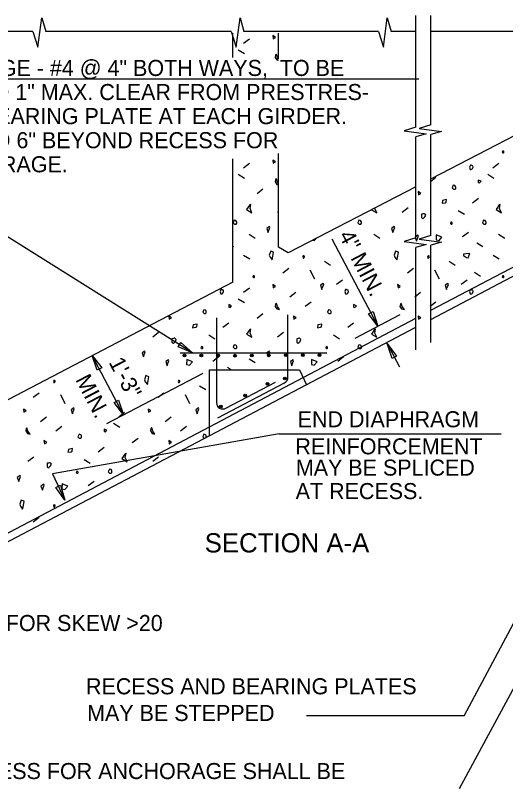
# Model space of a CAD drawing. Extents: x 0 to 22.7, y 0 to 15.7.
# Drawn here: x 3.45 to 6.629, y 5.449 to 10.447 of the extents above; entities that cross this region are included whole.
import ezdxf

# ---------------------------------------------------------------- set-up
doc = ezdxf.new("R2010")
doc.units = 0
for name, color, linetype in [('BRDG_ANNO_General-Notes', 7, 'Continuous'), ('BRDG_BASE_Obj-Line', 7, 'Continuous'), ('BRDG_BASE_Pattern', 7, 'Continuous'), ('BRDG_BASE_Rebar', 7, 'Continuous')]:
    doc.layers.add(name, color=color, linetype=linetype)

msp = doc.modelspace()

# ---------------------------------------------------------------- linework, layer by layer
at = {"layer": 'BRDG_ANNO_General-Notes'}
for p, q in [((6.0675, 10.0336), (2.7891, 10.0336)), ((4.5997, 8.2579), (2.7891, 9.3907)), ((5.503, 8.9974), (5.8017, 8.4298)), ((5.9439, 8.5038), (5.6511, 8.3507)), ((5.7404, 8.5105), (5.7698, 8.526)), ((5.8017, 8.4298), (5.7404, 8.5105)), ((5.7698, 8.526), (5.8017, 8.4298)), ((4.5061, 8.2968), (4.5237, 8.3251)), ((4.5997, 8.2579), (4.5061, 8.2968)), ((4.5237, 8.3251), (4.5997, 8.2579)), ((5.8609, 8.3171), (5.9403, 8.1663)), ((5.8928, 8.2208), (5.8609, 8.3171)), ((5.8609, 8.3171), (5.9222, 8.2364)), ((4.1515, 7.854), (3.9493, 8.2408)), ((3.9809, 8.1444), (3.9493, 8.2408)), ((3.9493, 8.2408), (4.0104, 8.1599)), ((5.9222, 8.2364), (5.8928, 8.2208)), ((4.0104, 8.1599), (3.9809, 8.1444)), ((4.6656, 8.1228), (4.0408, 7.7961)), ((4.0904, 7.9349), (4.1199, 7.9504)), ((4.1199, 7.9504), (4.1515, 7.854)), ((4.1515, 7.854), (4.0904, 7.9349)), ((5.1611, 7.7313), (3.6905, 7.473)), ((5.1611, 7.7313), (6.5995, 7.7313)), ((6.3616, 5.9025), (7.2128, 7.5057)), ((3.6905, 7.473), (3.7699, 7.3006)), ((3.7129, 7.3844), (3.7432, 7.3984)), ((3.7432, 7.3984), (3.7699, 7.3006)), ((3.7699, 7.3006), (3.7129, 7.3844)), ((6.3306, 5.43), (7.1358, 6.9271)), ((6.3616, 5.9025), (5.3378, 5.9025))]:
    msp.add_line(p, q, dxfattribs=at)
at = {"layer": 'BRDG_BASE_Obj-Line'}
for p, q in [((6.0466, 10.1917), (6.0466, 10.4467)), ((6.1455, 10.1917), (6.1455, 10.4467)), ((3.5964, 10.2407), (3.6219, 10.4317)), ((3.6219, 10.4317), (3.6476, 10.3412)), ((4.8815, 10.2406), (4.907, 10.4317)), ((4.907, 10.4317), (4.9327, 10.3412)), ((5.8365, 10.2407), (5.862, 10.4317)), ((5.862, 10.4317), (5.8877, 10.3412)), ((3.5639, 10.3412), (2.6926, 10.3412)), ((3.5639, 10.3412), (3.5964, 10.2407)), ((4.2125, 10.3412), (3.6476, 10.3412)), ((4.849, 10.3412), (4.2125, 10.3412)), ((4.849, 10.3412), (4.8815, 10.2406)), ((4.8611, 10.1728), (4.8611, 10.332)), ((5.804, 10.3412), (4.9327, 10.3412)), ((5.157, 10.1661), (5.157, 10.332)), ((5.804, 10.3412), (5.8365, 10.2407)), ((6.0467, 10.3412), (5.8877, 10.3412)), ((6.0466, 9.7217), (6.0466, 10.332)), ((6.6021, 10.3412), (6.1455, 10.3412)), ((6.1455, 9.7369), (6.1455, 10.332)), ((7.2386, 10.3412), (6.6021, 10.3412)), ((7.0631, 9.8613), (6.1473, 9.3866)), ((6.0466, 9.7217), (5.9708, 9.6971)), ((5.9708, 9.6971), (6.1144, 9.678)), ((6.1455, 9.7369), (6.0697, 9.7123)), ((6.0697, 9.7123), (6.2134, 9.6932)), ((6.1144, 9.678), (6.0466, 9.6587)), ((6.0466, 9.0042), (6.0466, 9.6587)), ((6.2134, 9.6932), (6.1455, 9.6739)), ((6.1455, 9.0194), (6.1455, 9.6739)), ((5.157, 8.9422), (5.157, 9.5498)), ((4.8611, 8.7151), (4.8611, 9.5166)), ((6.047, 9.3346), (5.219, 8.9054)), ((6.144, 8.4744), (7.5139, 9.1952)), ((6.0466, 9.0042), (5.9708, 8.9795)), ((6.1455, 9.0194), (6.0697, 8.9947)), ((5.9708, 8.9795), (6.1144, 8.9605)), ((6.1144, 8.9605), (6.0466, 8.9411)), ((6.0697, 8.9947), (6.2134, 8.9757)), ((6.2134, 8.9757), (6.1455, 8.9563)), ((6.1455, 8.3238), (6.1455, 8.9563)), ((5.219, 8.9054), (5.157, 8.9422)), ((6.0466, 8.2762), (6.0466, 8.9411)), ((4.8611, 8.7151), (3.3593, 7.9299)), ((2.6161, 6.6182), (6.0466, 8.4231)), ((4.7089, 7.7195), (4.7089, 8.1476)), ((4.7089, 8.1476), (5.2934, 8.1476)), ((5.2934, 8.1476), (5.3384, 8.0497))]:
    msp.add_line(p, q, dxfattribs=at)
at = {"layer": 'BRDG_BASE_Pattern'}
for p, q in [((4.9677, 10.2934), (4.9292, 10.2641)), ((4.8957, 10.2241), (4.9353, 10.1991)), ((4.9677, 9.4854), (4.9292, 9.4561)), ((6.5853, 9.4854), (6.5468, 9.4561)), ((4.8957, 9.4161), (4.9353, 9.3911)), ((6.5133, 9.4161), (6.5529, 9.3911)), ((6.1776, 9.3946), (6.1391, 9.3653)), ((5.0559, 9.3182), (5.0174, 9.2889)), ((6.4526, 9.2584), (6.4141, 9.2291)), ((5.9968, 9.1972), (5.9583, 9.1679)), ((5.157, 9.1736), (5.1495, 9.1679)), ((6.3222, 9.1815), (6.3618, 9.1566)), ((4.9662, 9.0267), (5.0057, 9.0018)), ((5.775, 9.0267), (5.8145, 9.0018)), ((6.3878, 9.0386), (6.3493, 9.0093)), ((6.5838, 9.0267), (6.6233, 9.0018)), ((4.8611, 8.9494), (4.8649, 8.947)), ((6.4429, 8.972), (6.4825, 8.947)), ((4.9303, 8.8915), (4.9698, 8.8664)), ((5.454, 8.8522), (5.4935, 8.8272)), ((6.2628, 8.8522), (6.3023, 8.8272)), ((6.5478, 8.8915), (6.5874, 8.8664)), ((5.2227, 8.8045), (5.1842, 8.7752)), ((5.36, 8.7956), (5.3893, 8.7368)), ((6.0315, 8.8045), (5.993, 8.7752)), ((6.1688, 8.7956), (6.1981, 8.7368)), ((6.4279, 8.7799), (6.4674, 8.7549)), ((5.5707, 8.7294), (5.5322, 8.7002)), ((6.3795, 8.7294), (6.341, 8.7002)), ((4.9677, 8.6774), (4.9292, 8.6482)), ((5.2694, 8.6479), (5.2309, 8.6186)), ((6.0782, 8.6479), (6.0397, 8.6186)), ((4.8957, 8.6082), (4.9353, 8.5832)), ((5.3689, 8.5867), (5.3303, 8.5574)), ((6.1776, 8.5867), (6.1391, 8.5574)), ((5.0559, 8.5102), (5.0174, 8.4809)), ((4.835, 8.4505), (4.7965, 8.4211)), ((5.6438, 8.4505), (5.6053, 8.4211)), ((4.3792, 8.3893), (4.3407, 8.36)), ((4.7046, 8.3735), (4.7442, 8.3486)), ((5.188, 8.3893), (5.1495, 8.36)), ((5.5134, 8.3735), (5.553, 8.3486)), ((4.7702, 8.2306), (4.7317, 8.2014)), ((4.9662, 8.2187), (5.0057, 8.1939)), ((5.579, 8.2306), (5.5405, 8.2014)), ((4.8253, 8.1641), (4.8515, 8.1476)), ((3.6052, 7.9965), (3.5667, 7.9672)), ((4.414, 7.9965), (4.3754, 7.9672)), ((4.6452, 8.0442), (4.6848, 8.0192)), ((3.7424, 7.9876), (3.7718, 7.9288)), ((4.5512, 7.9876), (4.5805, 7.9288)), ((4.1589, 7.8695), (4.1204, 7.8402)), ((3.6518, 7.8399), (3.6133, 7.8107)), ((4.087, 7.8003), (4.1266, 7.7753)), ((4.4606, 7.8399), (4.4221, 7.8107)), ((3.7512, 7.7787), (3.7128, 7.7494)), ((4.5601, 7.7787), (4.5216, 7.7494)), ((4.2472, 7.7022), (4.2086, 7.673)), ((4.0263, 7.6425), (3.9877, 7.6132)), ((3.5704, 7.5813), (3.5319, 7.552)), ((3.8958, 7.5656), (3.9354, 7.5406)), ((4.3792, 7.5813), (4.3407, 7.552)), ((3.9614, 7.4227), (3.9229, 7.3934)), ((3.6052, 7.1885), (3.5667, 7.1593))]:
    msp.add_line(p, q, dxfattribs=at)
for points in [[(5.12, 10.316), (5.1229, 10.2953), (5.1377, 10.3042)], [(6.6104, 9.567), (6.6067, 9.5589), (6.611, 9.5544), (6.6164, 9.5544), (6.6185, 9.5568), (6.6185, 9.5611), (6.6178, 9.5632), (6.6155, 9.5656)], [(5.12, 9.508), (5.1229, 9.4873), (5.1377, 9.4962)], [(6.3949, 9.4623), (6.3996, 9.4476), (6.4038, 9.4476), (6.4098, 9.4491), (6.4142, 9.4533), (6.4184, 9.4623), (6.4172, 9.4711), (6.4098, 9.4726), (6.4067, 9.4757), (6.4008, 9.4757)], [(6.4523, 9.3783), (6.4516, 9.3624), (6.4611, 9.3602), (6.4703, 9.3709)], [(6.0621, 9.3034), (6.0651, 9.2828), (6.0798, 9.2917)], [(6.2899, 9.345), (6.2825, 9.3288), (6.2911, 9.3198), (6.3018, 9.3198), (6.3061, 9.3245), (6.3061, 9.3331), (6.3046, 9.3374), (6.3001, 9.3421)], [(6.2203, 9.2461), (6.2173, 9.2285), (6.238, 9.2315), (6.2439, 9.2343), (6.2468, 9.252)], [(4.9706, 9.2176), (4.9501, 9.1867), (4.9847, 9.166), (4.9721, 9.194), (4.9774, 9.2197)], [(6.5882, 9.2176), (6.5677, 9.1867), (6.6023, 9.166), (6.5896, 9.194), (6.595, 9.2197)], [(6.0833, 9.157), (6.0833, 9.1347), (6.0934, 9.1275), (6.0966, 9.1304), (6.1052, 9.1393), (6.1111, 9.1511), (6.1068, 9.157), (6.1009, 9.1598), (6.098, 9.1598), (6.0922, 9.1582)], [(4.8692, 9.118), (4.8618, 9.1018), (4.8704, 9.0928), (4.881, 9.0928), (4.8853, 9.0976), (4.8853, 9.1061), (4.8839, 9.1104), (4.8793, 9.1152)], [(5.678, 9.118), (5.6705, 9.1018), (5.6792, 9.0928), (5.6898, 9.0928), (5.6941, 9.0976), (5.6941, 9.1061), (5.6927, 9.1104), (5.6881, 9.1152)], [(6.2752, 9.1055), (6.2715, 9.0974), (6.2758, 9.0929), (6.2811, 9.0929), (6.2832, 9.0953), (6.2832, 9.0996), (6.2825, 9.1017), (6.2802, 9.1041)], [(6.4868, 9.118), (6.4793, 9.1018), (6.488, 9.0928), (6.4986, 9.0928), (6.5029, 9.0976), (6.5029, 9.1061), (6.5015, 9.1104), (6.4969, 9.1152)], [(5.0802, 9.0648), (5.0893, 9.0383), (5.0893, 9.0411), (5.1011, 9.0707), (5.0981, 9.0766)], [(5.889, 9.0648), (5.8981, 9.0383), (5.8981, 9.0411), (5.9099, 9.0707), (5.9069, 9.0766)], [(6.0427, 9.0083), (6.0519, 8.9817), (6.0519, 8.9846), (6.0636, 9.0142), (6.0606, 9.0201)], [(6.1798, 9.0223), (6.1784, 8.9907), (6.1975, 8.9863), (6.2159, 9.0076)], [(5.106, 8.9174), (5.0971, 8.8908), (5.1017, 8.8776), (5.1149, 8.8599), (5.1208, 8.8835), (5.1252, 8.9101)], [(5.9148, 8.9174), (5.9059, 8.8908), (5.9105, 8.8776), (5.9237, 8.8599), (5.9296, 8.8835), (5.934, 8.9101)], [(6.3746, 8.8998), (6.3569, 8.8983), (6.3569, 8.8895), (6.3761, 8.8762), (6.3865, 8.8748), (6.3968, 8.9028)], [(5.3144, 8.8796), (5.3167, 8.8722), (5.3189, 8.8722), (5.3219, 8.8729), (5.324, 8.8751), (5.3261, 8.8796), (5.3256, 8.884), (5.3219, 8.8847), (5.3203, 8.8863), (5.3173, 8.8863)], [(6.1232, 8.8796), (6.1255, 8.8722), (6.1277, 8.8722), (6.1306, 8.8729), (6.1328, 8.8751), (6.1349, 8.8796), (6.1344, 8.884), (6.1306, 8.8847), (6.1291, 8.8863), (6.1261, 8.8863)], [(4.9929, 8.7591), (4.9892, 8.7509), (4.9935, 8.7465), (4.9988, 8.7465), (5.0009, 8.7488), (5.0009, 8.7531), (5.0002, 8.7553), (4.998, 8.7577)], [(6.6104, 8.7591), (6.6067, 8.7509), (6.611, 8.7465), (6.6164, 8.7465), (6.6185, 8.7488), (6.6185, 8.7531), (6.6178, 8.7553), (6.6155, 8.7577)], [(5.12, 8.7001), (5.1229, 8.6794), (5.1377, 8.6883)], [(5.4288, 8.6957), (5.4379, 8.6692), (5.4379, 8.672), (5.4497, 8.7016), (5.4467, 8.7075)], [(5.9287, 8.7001), (5.9317, 8.6794), (5.9465, 8.6883)], [(6.2376, 8.6957), (6.2467, 8.6692), (6.2467, 8.672), (6.2585, 8.7016), (6.2555, 8.7075)], [(4.7773, 8.6544), (4.782, 8.6396), (4.7862, 8.6396), (4.7922, 8.6411), (4.7966, 8.6454), (4.8008, 8.6544), (4.7996, 8.6631), (4.7922, 8.6647), (4.7891, 8.6677), (4.7832, 8.6677)], [(5.5861, 8.6544), (5.5908, 8.6396), (5.595, 8.6396), (5.601, 8.6411), (5.6054, 8.6454), (5.6096, 8.6544), (5.6084, 8.6631), (5.601, 8.6647), (5.5979, 8.6677), (5.592, 8.6677)], [(6.3949, 8.6544), (6.3996, 8.6396), (6.4038, 8.6396), (6.4098, 8.6411), (6.4142, 8.6454), (6.4184, 8.6544), (6.4172, 8.6631), (6.4098, 8.6647), (6.4067, 8.6677), (6.4008, 8.6677)], [(4.8347, 8.5703), (4.834, 8.5545), (4.8435, 8.5523), (4.8528, 8.563)], [(5.1379, 8.5747), (5.1347, 8.5581), (5.1457, 8.5419), (5.1641, 8.5382), (5.1494, 8.5578), (5.1431, 8.578)], [(5.6435, 8.5703), (5.6428, 8.5545), (5.6523, 8.5523), (5.6616, 8.563)], [(5.9467, 8.5747), (5.9435, 8.5581), (5.9545, 8.5419), (5.9729, 8.5382), (5.9582, 8.5578), (5.9519, 8.578)], [(4.6723, 8.537), (4.6649, 8.5208), (4.6736, 8.5119), (4.6842, 8.5119), (4.6885, 8.5166), (4.6885, 8.5252), (4.687, 8.5294), (4.6824, 8.5342)], [(5.4811, 8.537), (5.4737, 8.5208), (5.4824, 8.5119), (5.493, 8.5119), (5.4973, 8.5166), (5.4973, 8.5252), (5.4958, 8.5294), (5.4912, 8.5342)], [(5.2533, 8.4955), (5.2562, 8.4748), (5.271, 8.4837)], [(6.0621, 8.4955), (6.0651, 8.4748), (6.0798, 8.4837)], [(4.6028, 8.4382), (4.5998, 8.4205), (4.6204, 8.4235), (4.6263, 8.4264), (4.6293, 8.4441)], [(4.9706, 8.4096), (4.9501, 8.3788), (4.9847, 8.358), (4.9721, 8.386), (4.9774, 8.4118)], [(5.4116, 8.4382), (5.4085, 8.4205), (5.4292, 8.4235), (5.4351, 8.4264), (5.438, 8.4441)], [(5.7794, 8.4096), (5.7589, 8.3788), (5.7935, 8.358), (5.7808, 8.386), (5.7862, 8.4118)], [(4.4657, 8.3491), (4.4657, 8.3267), (4.4759, 8.3195), (4.479, 8.3224), (4.4876, 8.3313), (4.4935, 8.3431), (4.4893, 8.3491), (4.4833, 8.3519), (4.4805, 8.3519), (4.4747, 8.3503)], [(5.2745, 8.3491), (5.2745, 8.3267), (5.2847, 8.3195), (5.2878, 8.3224), (5.2964, 8.3313), (5.3023, 8.3431), (5.298, 8.3491), (5.2921, 8.3519), (5.2893, 8.3519), (5.2834, 8.3503)], [(4.6576, 8.2976), (4.6539, 8.2894), (4.6582, 8.2849), (4.6635, 8.2849), (4.6657, 8.2873), (4.6657, 8.2916), (4.6649, 8.2937), (4.6627, 8.2961)], [(4.8692, 8.3101), (4.8618, 8.2939), (4.8704, 8.2849), (4.881, 8.2849), (4.8853, 8.2896), (4.8853, 8.2982), (4.8839, 8.3024), (4.8793, 8.3072)], [(5.4664, 8.2976), (5.4627, 8.2894), (5.467, 8.2849), (5.4723, 8.2849), (5.4745, 8.2873), (5.4745, 8.2916), (5.4737, 8.2937), (5.4715, 8.2961)], [(5.678, 8.3101), (5.6705, 8.2939), (5.6792, 8.2849), (5.6898, 8.2849), (5.6941, 8.2896), (5.6941, 8.2982), (5.6927, 8.3024), (5.6881, 8.3072)], [(4.2714, 8.2569), (4.2805, 8.2303), (4.2805, 8.2332), (4.2923, 8.2628), (4.2893, 8.2686)], [(5.0802, 8.2569), (5.0893, 8.2303), (5.0893, 8.2332), (5.1011, 8.2628), (5.0981, 8.2686)], [(4.4252, 8.2003), (4.4343, 8.1738), (4.4343, 8.1766), (4.446, 8.2062), (4.443, 8.2121)], [(4.5622, 8.2144), (4.5608, 8.1827), (4.5799, 8.1783), (4.5983, 8.1996)], [(5.234, 8.2003), (5.2431, 8.1738), (5.2431, 8.1766), (5.2548, 8.2062), (5.2518, 8.2121)], [(5.371, 8.2144), (5.3696, 8.1827), (5.3887, 8.1783), (5.4071, 8.1996)], [(4.2973, 8.1094), (4.2883, 8.0829), (4.2929, 8.0696), (4.3061, 8.0519), (4.312, 8.0755), (4.3164, 8.1021)], [(3.6968, 8.0716), (3.6992, 8.0642), (3.7012, 8.0642), (3.7043, 8.065), (3.7065, 8.0671), (3.7086, 8.0716), (3.708, 8.076), (3.7043, 8.0768), (3.7027, 8.0783), (3.6998, 8.0783)], [(4.5056, 8.0716), (4.5079, 8.0642), (4.5101, 8.0642), (4.5131, 8.065), (4.5152, 8.0671), (4.5174, 8.0716), (4.5168, 8.076), (4.5131, 8.0768), (4.5115, 8.0783), (4.5085, 8.0783)], [(3.8112, 7.8878), (3.8204, 7.8612), (3.8204, 7.8641), (3.8321, 7.8936), (3.8291, 7.8995)], [(4.62, 7.8878), (4.6292, 7.8612), (4.6292, 7.8641), (4.6409, 7.8936), (4.6379, 7.8995)], [(3.5024, 7.8921), (3.5054, 7.8715), (3.5202, 7.8803)], [(4.3112, 7.8921), (4.3142, 7.8715), (4.329, 7.8803)], [(3.5204, 7.7668), (3.5171, 7.7502), (3.5281, 7.7339), (3.5466, 7.7303), (3.5318, 7.7498), (3.5255, 7.7701)], [(4.0259, 7.7623), (4.0252, 7.7466), (4.0347, 7.7443), (4.044, 7.755)], [(4.3292, 7.7668), (4.3259, 7.7502), (4.3369, 7.7339), (4.3553, 7.7303), (4.3406, 7.7498), (4.3343, 7.7701)], [(3.8635, 7.7291), (3.8561, 7.7129), (3.8648, 7.7039), (3.8754, 7.7039), (3.8797, 7.7086), (3.8797, 7.7172), (3.8782, 7.7215), (3.8736, 7.7262)], [(3.6357, 7.6875), (3.6386, 7.6669), (3.6534, 7.6757)], [(4.4445, 7.6875), (4.4474, 7.6669), (4.4622, 7.6757)], [(3.794, 7.6302), (3.791, 7.6126), (3.8117, 7.6155), (3.8175, 7.6184), (3.8205, 7.6361)], [(4.1619, 7.6017), (4.1412, 7.5708), (4.1759, 7.5501), (4.1633, 7.5781), (4.1686, 7.6038)], [(3.657, 7.5411), (3.657, 7.5187), (3.6671, 7.5116), (3.6702, 7.5145), (3.6789, 7.5233), (3.6847, 7.5352), (3.6805, 7.5411), (3.6745, 7.5439), (3.6717, 7.5439), (3.6659, 7.5423)], [(4.0604, 7.5021), (4.053, 7.4859), (4.0616, 7.4769), (4.0722, 7.4769), (4.0766, 7.4816), (4.0766, 7.4903), (4.0751, 7.4945), (4.0705, 7.4993)], [(3.4626, 7.449), (3.4717, 7.4223), (3.4717, 7.4252), (3.4835, 7.4548), (3.4805, 7.4607)], [(3.8488, 7.4896), (3.8451, 7.4815), (3.8494, 7.477), (3.8547, 7.477), (3.8569, 7.4793), (3.8569, 7.4836), (3.8561, 7.4858), (3.8539, 7.4881)], [(3.6164, 7.3924), (3.6255, 7.3658), (3.6255, 7.3686), (3.6372, 7.3983), (3.6343, 7.4042)], [(3.7534, 7.4065), (3.752, 7.3748), (3.7711, 7.3703), (3.7895, 7.3917)], [(3.4885, 7.3015), (3.4795, 7.2749), (3.4841, 7.2617), (3.4973, 7.244), (3.5032, 7.2676), (3.5076, 7.2941)], [(3.6968, 7.2636), (3.6992, 7.2562), (3.7012, 7.2562), (3.7043, 7.257), (3.7065, 7.2592), (3.7086, 7.2636), (3.708, 7.2681), (3.7043, 7.2688), (3.7027, 7.2704), (3.6998, 7.2704)]]:
    msp.add_lwpolyline(points, close=True, dxfattribs=at)
for points in [[(5.1379, 10.1906), (5.1347, 10.174), (5.1457, 10.1578), (5.157, 10.1556)], [(5.157, 10.1635), (5.1494, 10.1736), (5.1431, 10.1939), (5.1379, 10.1906)], [(5.1379, 9.3827), (5.1347, 9.366), (5.1457, 9.3498), (5.157, 9.3476)], [(5.157, 9.3556), (5.1494, 9.3657), (5.1431, 9.3859), (5.1379, 9.3827)], [(5.7602, 9.1859), (5.7935, 9.166), (5.7808, 9.194), (5.7815, 9.1969)], [(5.3792, 8.9884), (5.3887, 8.9863), (5.3998, 8.9991)], [(4.4446, 8.4949), (4.4474, 8.4748), (4.4622, 8.4837), (4.445, 8.4951)], [(4.6723, 7.7291), (4.6649, 7.7129), (4.6736, 7.7039), (4.6792, 7.7039)], [(4.6885, 7.7088), (4.6885, 7.7172), (4.687, 7.7215), (4.6824, 7.7262), (4.6723, 7.7291)]]:
    msp.add_lwpolyline(points, dxfattribs=at)
at = {"layer": 'BRDG_BASE_Rebar'}
for p, q in [((6.1497, 8.5355), (7.4903, 9.2409)), ((5.2178, 8.1004), (5.2178, 8.5049)), ((2.5968, 6.6661), (6.0472, 8.4816)), ((4.7545, 8.4848), (4.7545, 7.9346)), ((4.5183, 8.2579), (5.4692, 8.2579)), ((4.7624, 7.8356), (5.1955, 8.0635)), ((4.8156, 7.8978), (5.1368, 8.0667))]:
    msp.add_line(p, q, dxfattribs=at)
for centre, radius in [((4.5469, 8.2408), 0.0089), ((4.5469, 8.2408), 0.00593), ((4.6563, 8.2408), 0.0089), ((4.6563, 8.2408), 0.00593), ((4.7657, 8.2408), 0.0089), ((4.7657, 8.2408), 0.00593), ((4.8743, 8.2391), 0.0089), ((4.9843, 8.2401), 0.0089), ((4.9843, 8.2401), 0.00593), ((5.0943, 8.2411), 0.0089), ((5.0943, 8.2411), 0.00593), ((5.2043, 8.2421), 0.0089), ((5.2043, 8.2421), 0.00593), ((5.3136, 8.2421), 0.0089), ((5.3136, 8.2421), 0.00593), ((5.423, 8.2421), 0.0089), ((5.423, 8.2421), 0.00593), ((4.5469, 8.2408), 0.00297), ((4.6563, 8.2408), 0.00297), ((4.7657, 8.2408), 0.00297), ((4.8743, 8.2391), 0.00593), ((4.8743, 8.2391), 0.00297), ((4.9843, 8.2401), 0.00297), ((5.0943, 8.2411), 0.00297), ((5.2043, 8.2421), 0.00297), ((5.3136, 8.2421), 0.00297), ((5.423, 8.2421), 0.00297), ((5.1977, 8.0903), 0.0089), ((5.1977, 8.0903), 0.00593), ((5.0854, 8.0569), 0.0089), ((5.0854, 8.0569), 0.00593), ((5.0854, 8.0569), 0.00297), ((5.1977, 8.0903), 0.00297), ((4.9396, 7.9807), 0.0089), ((4.9396, 7.9807), 0.00593), ((4.9396, 7.9807), 0.00297), ((4.7832, 7.9098), 0.0089), ((4.7832, 7.9098), 0.00593), ((4.7832, 7.9098), 0.00297)]:
    msp.add_circle(centre, radius, dxfattribs=at)
for centre, start, end in [((5.1761, 8.1004), 297.7504, 0), ((4.7962, 7.9346), 180, 297.7519)]:
    msp.add_arc(centre, 0.0417, start, end, dxfattribs=at)

# ---------------------------------------------------------------- texts
at = {"layer": 'BRDG_ANNO_General-Notes'}
for s, height, p in [('GRILLAGE - #4 @ 4" BOTH WAYS,  TO BE', 0.104167, (2.8535, 10.0537)), ('PLACED 1" MAX. CLEAR FROM PRESTRES-', 0.104167, (2.8535, 9.8974)), ('SING BEARING PLATE AT EACH GIRDER.', 0.104167, (2.8535, 9.7412)), ('EXTEND 6" BEYOND RECESS FOR', 0.104167, (2.8535, 9.5849)), ('ANCHORAGE.', 0.10417, (2.8535, 9.4287)), ('END DIAPHRAGM ', 0.104115, (5.2811, 7.7742)), ('REINFORCEMENT', 0.104115, (5.266, 7.5987)), ('MAY BE SPLICED ', 0.104115, (5.2691, 7.4606)), ('AT RECESS.', 0.10411, (5.268, 7.3083)), ('SECTION A-A', 0.124937, (4.6781, 6.962)), ('*OMIT FOR SKEW >20', 0.104115, (2.9474, 6.4523)), ('RECESS AND BEARING PLATES', 0.104167, (3.9081, 6.0416)), ('MAY BE STEPPED', 0.104167, (3.9155, 5.8684)), ('RECESS FOR ANCHORAGE SHALL BE', 0.104167, (3.0429, 5.4917))]:
    msp.add_text(s, height=height, dxfattribs=at).set_placement(p)
for s, height, rotation, p in [('4" MIN.', 0.10411, 297.7511, (5.5442, 9.0196)), ('1\'-3"', 0.10417, 297.5987, (4.0535, 8.1961)), ('MIN.', 0.10417, 297.5987, (3.8372, 8.0837))]:
    msp.add_text(s, height=height, rotation=rotation, dxfattribs=at).set_placement(p)

doc.saveas('drawing.dxf')
